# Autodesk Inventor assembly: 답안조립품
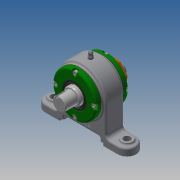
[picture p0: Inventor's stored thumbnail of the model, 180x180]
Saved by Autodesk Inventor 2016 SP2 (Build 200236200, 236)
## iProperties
Created: 2019-05
Part Number: 답안조립품
Document SubType Name: Assembly
Designer: EZ
Author: EZ
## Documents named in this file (13)
- Y:\490504V1015\답안조립품.iam
- Y:\490504V1015\본체.ipt
- Y:\490504V1015\개스킷.ipt
- Y:\490504V1015\커버.ipt
- Y:\490504V1015\볼트 M4.ipt
- Y:\490504V1015\오일 실 28 40 5 B.ipt
- Y:\490504V1015\축.ipt
- Y:\490504V1015\앵귤러 볼 베어링 7205.ipt
- Y:\490504V1015\칼라.ipt
- Y:\490504V1015\베어링너트.ipt
- Y:\490504V1015\그리스니플개스킷.ipt
- Y:\490504V1015\그리스니플 M6.ipt
- 그리스니플  M6.ipt
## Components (4 placed, 3 different names)
1. 개스킷:1
2. 개스킷:2
3. 그리스니플개스킷:1
4. 그리스니플  M6:1
